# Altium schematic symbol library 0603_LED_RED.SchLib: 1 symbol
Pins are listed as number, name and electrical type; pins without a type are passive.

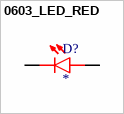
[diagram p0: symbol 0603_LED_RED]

## 0603_LED_RED
designator D?
MF: Wurth Elektronik; MP: 150060VS75000
footprint 0603_LED
pins: 1 NEG, 2 POS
